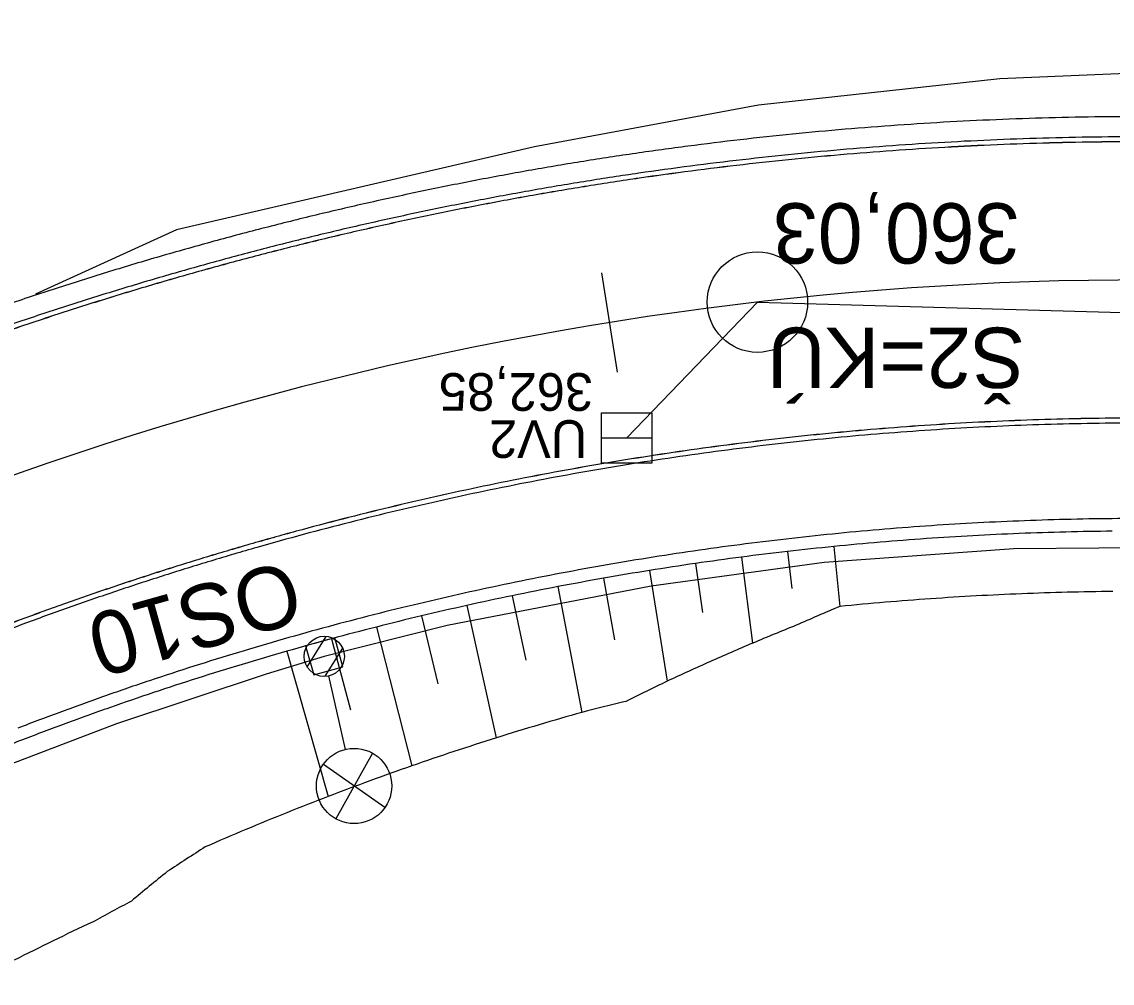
# Model space of a CAD drawing. Extents: x -783978 to -783565, y -1064821 to -1064596.
# Drawn here: x -783930.06 to -783908.35, y -1064751.46 to -1064732.32 of the extents above; entities that cross this region are included whole.
import ezdxf

# ---------------------------------------------------------------- set-up
doc = ezdxf.new("R2010")
doc.units = 0
for name, color, linetype in [('SO 01_31_01', 7, 'Continuous'), ('SO 01_50_01', 7, 'Continuous'), ('SO 01_86_02', 7, 'Continuous')]:
    doc.layers.add(name, color=color, linetype=linetype)

msp = doc.modelspace()

# ---------------------------------------------------------------- linework, layer by layer
at = {"layer": 'SO 01_31_01'}
msp.add_line((-783915.414, -1064737.9), (-783918.017, -1064740.603), dxfattribs=at)
for points in [[(-783915.414, -1064737.9), (-783878.441, -1064738.947), (-783868.99, -1064750.07)], [(-783918.517, -1064740.603), (-783918.517, -1064740.103), (-783917.517, -1064740.103), (-783917.517, -1064741.103), (-783918.517, -1064741.103), (-783918.517, -1064740.603), (-783917.517, -1064740.603)]]:
    msp.add_lwpolyline(points, dxfattribs=at)
msp.add_circle((-783915.414, -1064737.9), 1, dxfattribs=at)
at = {"layer": 'SO 01_50_01'}
for p, q in [((-783918.198, -1064739.294), (-783918.515, -1064737.319)), ((-783913.893, -1064742.765), (-783913.774, -1064743.959)), ((-783915.732, -1064742.977), (-783915.509, -1064744.689)), ((-783914.814, -1064742.864), (-783914.729, -1064743.599)), ((-783917.563, -1064743.243), (-783917.209, -1064745.446)), ((-783916.649, -1064743.103), (-783916.507, -1064744.081)), ((-783918.476, -1064743.397), (-783918.26, -1064744.626)), ((-783919.386, -1064743.564), (-783918.907, -1064746.067)), ((-783920.294, -1064743.745), (-783920.028, -1064745.03)), ((-783921.198, -1064743.939), (-783920.612, -1064746.574)), ((-783922.1, -1064744.147), (-783921.778, -1064745.497)), ((-783922.999, -1064744.368), (-783922.296, -1064747.133)), ((-783923.894, -1064744.603), (-783923.512, -1064746.017)), ((-783924.785, -1064744.851), (-783923.958, -1064747.741))]:
    msp.add_line(p, q, dxfattribs=at)
msp.add_lwpolyline([(-783892.218, -1064732.32), (-783899.264, -1064732.985), (-783903.473, -1064733.076), (-783906.328, -1064733.273), (-783910.587, -1064733.457), (-783915.392, -1064733.98), (-783919.851, -1064734.807), (-783926.976, -1064736.461), (-783929.783, -1064737.741)], dxfattribs=at)
for centre, radius, start, end in [((-783907.727, -1064804.458), 70.25, 93.14253, 93.99769), ((-783907.727, -1064804.458), 70.25, 93.14253, 93.99769), ((-783907.727, -1064804.458), 70.25, 93.14253, 93.99769), ((-783907.727, -1064804.458), 70.25, 92.28736, 93.14253), ((-783907.727, -1064804.458), 70.25, 92.28736, 93.14253), ((-783907.727, -1064804.458), 70.25, 92.28736, 93.14253), ((-783907.727, -1064804.458), 70.25, 91.4322, 92.28736), ((-783907.727, -1064804.458), 70.25, 91.4322, 92.28736), ((-783907.727, -1064804.458), 70.25, 91.4322, 92.28736), ((-783907.727, -1064804.458), 70.25, 90.57704, 91.4322), ((-783907.727, -1064804.458), 70.25, 90.57704, 91.4322), ((-783907.727, -1064804.458), 70.25, 90.57704, 91.4322), ((-783907.727, -1064804.458), 70.25, 89.72188, 90.57704), ((-783907.727, -1064804.458), 70.25, 89.72188, 90.57704), ((-783907.727, -1064804.458), 70.25, 89.72188, 90.57704), ((-783907.727, -1064804.458), 70.25, 95.70801, 96.56317), ((-783907.727, -1064804.458), 70.25, 95.70801, 96.56317), ((-783907.727, -1064804.458), 70.25, 95.70801, 96.56317), ((-783907.727, -1064804.458), 70.25, 94.85285, 95.70801), ((-783907.727, -1064804.458), 70.25, 94.85285, 95.70801), ((-783907.727, -1064804.458), 70.25, 94.85285, 95.70801), ((-783907.727, -1064804.458), 70.25, 93.99769, 94.85285), ((-783907.727, -1064804.458), 70.25, 93.99769, 94.85285), ((-783907.727, -1064804.458), 70.25, 93.99769, 94.85285), ((-783907.727, -1064804.458), 70.25, 97.41833, 98.27349), ((-783907.727, -1064804.458), 70.25, 97.41833, 98.27349), ((-783907.727, -1064804.458), 70.25, 97.41833, 98.27349), ((-783907.727, -1064804.458), 70.25, 96.56317, 97.41833), ((-783907.727, -1064804.458), 70.25, 96.56317, 97.41833), ((-783907.727, -1064804.458), 70.25, 96.56317, 97.41833), ((-783907.727, -1064804.458), 69.85, 93.99769, 94.85285), ((-783907.727, -1064804.458), 69.85, 93.14253, 93.99769), ((-783907.727, -1064804.458), 69.85, 92.28736, 93.14253), ((-783907.727, -1064804.458), 69.751, 92.28736, 93.14253), ((-783907.727, -1064804.458), 69.75, 92.28736, 93.14253), ((-783907.727, -1064804.458), 69.85, 91.4322, 92.28736), ((-783907.727, -1064804.458), 69.751, 91.4322, 92.28736), ((-783907.727, -1064804.458), 69.75, 91.4322, 92.28736), ((-783907.727, -1064804.458), 69.85, 90.57704, 91.4322), ((-783907.727, -1064804.458), 69.751, 90.57704, 91.4322), ((-783907.727, -1064804.458), 69.75, 90.57704, 91.4322), ((-783907.727, -1064804.458), 69.85, 89.72188, 90.57704), ((-783907.727, -1064804.458), 69.751, 89.72188, 90.57704), ((-783907.727, -1064804.458), 69.75, 89.72188, 90.57704), ((-783907.727, -1064804.458), 70.25, 98.27349, 99.12865), ((-783907.727, -1064804.458), 70.25, 98.27349, 99.12865), ((-783907.727, -1064804.458), 70.25, 98.27349, 99.12865), ((-783907.727, -1064804.458), 69.85, 95.70801, 96.56317), ((-783907.727, -1064804.458), 69.85, 94.85285, 95.70801), ((-783907.727, -1064804.458), 69.751, 94.85285, 95.70801), ((-783907.727, -1064804.458), 69.75, 94.85285, 95.70801), ((-783907.727, -1064804.458), 69.751, 93.99769, 94.85285), ((-783907.727, -1064804.458), 69.75, 93.99769, 94.85285), ((-783907.727, -1064804.458), 69.751, 93.14253, 93.99769), ((-783907.727, -1064804.458), 69.75, 93.14253, 93.99769), ((-783907.727, -1064804.458), 70.25, 99.12865, 99.98381), ((-783907.727, -1064804.458), 70.25, 99.12865, 99.98381), ((-783907.727, -1064804.458), 70.25, 99.12865, 99.98381), ((-783907.727, -1064804.458), 69.85, 97.41833, 98.27349), ((-783907.727, -1064804.458), 69.85, 96.56317, 97.41833), ((-783907.727, -1064804.458), 69.751, 96.56317, 97.41833), ((-783907.727, -1064804.458), 69.75, 96.56317, 97.41833), ((-783907.727, -1064804.458), 69.751, 95.70801, 96.56317), ((-783907.727, -1064804.458), 69.75, 95.70801, 96.56317), ((-783907.727, -1064804.458), 70.25, 99.98381, 100.83897), ((-783907.727, -1064804.458), 70.25, 99.98381, 100.83897), ((-783907.727, -1064804.458), 70.25, 99.98381, 100.83897), ((-783907.727, -1064804.458), 69.85, 98.27349, 99.12865), ((-783907.727, -1064804.458), 69.751, 98.27349, 99.12865), ((-783907.727, -1064804.458), 69.75, 98.27349, 99.12865), ((-783907.727, -1064804.458), 69.751, 97.41833, 98.27349), ((-783907.727, -1064804.458), 69.75, 97.41833, 98.27349), ((-783907.727, -1064804.458), 70.25, 101.69413, 102.5493), ((-783907.727, -1064804.458), 70.25, 101.69413, 102.5493), ((-783907.727, -1064804.458), 70.25, 101.69413, 102.5493), ((-783907.727, -1064804.458), 70.25, 100.83897, 101.69413), ((-783907.727, -1064804.458), 70.25, 100.83897, 101.69413), ((-783907.727, -1064804.458), 70.25, 100.83897, 101.69413), ((-783907.727, -1064804.458), 69.85, 99.98381, 100.83897), ((-783907.727, -1064804.458), 69.85, 99.12865, 99.98381), ((-783907.727, -1064804.458), 69.751, 99.12865, 99.98381), ((-783907.727, -1064804.458), 69.75, 99.12865, 99.98381), ((-783907.727, -1064804.458), 70.25, 102.5493, 103.40446), ((-783907.727, -1064804.458), 70.25, 102.5493, 103.40446), ((-783907.727, -1064804.458), 70.25, 102.5493, 103.40446), ((-783907.727, -1064804.458), 69.85, 100.83897, 101.69413), ((-783907.727, -1064804.458), 69.751, 99.98381, 100.83897), ((-783907.727, -1064804.458), 69.75, 99.98381, 100.83897), ((-783907.727, -1064804.458), 69.85, 101.69413, 102.5493), ((-783907.727, -1064804.458), 69.751, 100.83897, 101.69413), ((-783907.727, -1064804.458), 69.75, 100.83897, 101.69413), ((-783907.727, -1064804.458), 70.25, 103.40446, 104.25962), ((-783907.727, -1064804.458), 70.25, 103.40446, 104.25962), ((-783907.727, -1064804.458), 70.25, 103.40446, 104.25962), ((-783907.727, -1064804.458), 69.85, 102.5493, 103.40446), ((-783907.727, -1064804.458), 69.751, 101.69413, 102.5493), ((-783907.727, -1064804.458), 69.75, 101.69413, 102.5493), ((-783907.727, -1064804.458), 70.25, 104.25962, 105.11478), ((-783907.727, -1064804.458), 70.25, 104.25962, 105.11478), ((-783907.727, -1064804.458), 70.25, 104.25962, 105.11478), ((-783907.727, -1064804.458), 69.85, 103.40446, 104.25962), ((-783907.727, -1064804.458), 69.751, 102.5493, 103.40446), ((-783907.727, -1064804.458), 69.75, 102.5493, 103.40446), ((-783907.727, -1064804.458), 70.25, 105.11478, 105.96994), ((-783907.727, -1064804.458), 70.25, 105.11478, 105.96994), ((-783907.727, -1064804.458), 70.25, 105.11478, 105.96994), ((-783907.727, -1064804.458), 69.751, 103.40446, 104.25962), ((-783907.727, -1064804.458), 69.75, 103.40446, 104.25962), ((-783907.727, -1064804.458), 70.25, 105.96994, 106.8251), ((-783907.727, -1064804.458), 70.25, 105.96994, 106.8251), ((-783907.727, -1064804.458), 70.25, 105.96994, 106.8251), ((-783907.727, -1064804.458), 69.85, 104.25962, 105.11478), ((-783907.727, -1064804.458), 69.751, 104.25962, 105.11478), ((-783907.727, -1064804.458), 69.75, 104.25962, 105.11478), ((-783907.727, -1064804.458), 69.85, 105.11478, 105.96994), ((-783907.727, -1064804.458), 69.751, 105.11478, 105.96994), ((-783907.727, -1064804.458), 69.75, 105.11478, 105.96994), ((-783907.727, -1064804.458), 70.25, 106.8251, 107.68026), ((-783907.727, -1064804.458), 70.25, 106.8251, 107.68026), ((-783907.727, -1064804.458), 70.25, 106.8251, 107.68026), ((-783907.727, -1064804.458), 69.85, 105.96994, 106.8251), ((-783907.727, -1064804.458), 69.751, 105.96994, 106.8251), ((-783907.727, -1064804.458), 69.75, 105.96994, 106.8251), ((-783907.727, -1064804.458), 67, 86.89792, 119.07174), ((-783907.727, -1064804.458), 70.25, 107.68026, 108.53542), ((-783907.727, -1064804.458), 70.25, 107.68026, 108.53542), ((-783907.727, -1064804.458), 70.25, 107.68026, 108.53542), ((-783907.727, -1064804.458), 69.85, 106.8251, 107.68026), ((-783907.727, -1064804.458), 69.751, 106.8251, 107.68026), ((-783907.727, -1064804.458), 69.75, 106.8251, 107.68026), ((-783907.727, -1064804.458), 70.25, 108.53542, 109.39058), ((-783907.727, -1064804.458), 70.25, 108.53542, 109.39058), ((-783907.727, -1064804.458), 70.25, 108.53542, 109.39058), ((-783907.727, -1064804.458), 69.85, 107.68026, 108.53542), ((-783907.727, -1064804.458), 69.751, 107.68026, 108.53542), ((-783907.727, -1064804.458), 69.75, 107.68026, 108.53542), ((-783907.727, -1064804.458), 69.85, 108.53542, 109.39058), ((-783907.727, -1064804.458), 69.751, 108.53542, 109.39058), ((-783907.727, -1064804.458), 69.75, 108.53542, 109.39058), ((-783907.727, -1064804.458), 64.25, 91.4322, 92.28736), ((-783907.727, -1064804.458), 64.249, 91.4322, 92.28736), ((-783907.727, -1064804.458), 64.25, 90.57704, 91.4322), ((-783907.727, -1064804.458), 64.249, 90.57704, 91.4322), ((-783907.727, -1064804.458), 64.25, 89.72188, 90.57704), ((-783907.727, -1064804.458), 64.249, 89.72188, 90.57704), ((-783907.727, -1064804.458), 64.25, 94.85285, 95.70801), ((-783907.727, -1064804.458), 64.249, 94.85285, 95.70801), ((-783907.727, -1064804.458), 64.25, 93.99769, 94.85285), ((-783907.727, -1064804.458), 64.249, 93.99769, 94.85285), ((-783907.727, -1064804.458), 64.25, 93.14253, 93.99769), ((-783907.727, -1064804.458), 64.249, 93.14253, 93.99769), ((-783907.727, -1064804.458), 64.15, 93.14253, 93.99769), ((-783907.727, -1064804.458), 64.25, 92.28736, 93.14253), ((-783907.727, -1064804.458), 64.249, 92.28736, 93.14253), ((-783907.727, -1064804.458), 64.15, 92.28736, 93.14253), ((-783907.727, -1064804.458), 64.15, 91.4322, 92.28736), ((-783907.727, -1064804.458), 64.15, 90.57704, 91.4322), ((-783907.727, -1064804.458), 64.15, 89.72188, 90.57704), ((-783907.727, -1064804.458), 64.25, 96.56317, 97.41833), ((-783907.727, -1064804.458), 64.249, 96.56317, 97.41833), ((-783907.727, -1064804.458), 64.25, 95.70801, 96.56317), ((-783907.727, -1064804.458), 64.249, 95.70801, 96.56317), ((-783907.727, -1064804.458), 64.15, 95.70801, 96.56317), ((-783907.727, -1064804.458), 64.15, 94.85285, 95.70801), ((-783907.727, -1064804.458), 64.15, 93.99769, 94.85285), ((-783907.727, -1064804.458), 64.25, 98.27349, 99.12865), ((-783907.727, -1064804.458), 64.249, 98.27349, 99.12865), ((-783907.727, -1064804.458), 64.25, 97.41833, 98.27349), ((-783907.727, -1064804.458), 64.249, 97.41833, 98.27349), ((-783907.727, -1064804.458), 64.15, 97.41833, 98.27349), ((-783907.727, -1064804.458), 64.15, 96.56317, 97.41833), ((-783907.727, -1064804.458), 64.25, 99.12865, 99.98381), ((-783907.727, -1064804.458), 64.249, 99.12865, 99.98381), ((-783907.727, -1064804.458), 64.15, 98.27349, 99.12865), ((-783907.727, -1064804.458), 64.25, 99.98381, 100.83897), ((-783907.727, -1064804.458), 64.249, 99.98381, 100.83897), ((-783907.727, -1064804.458), 64.15, 99.98381, 100.83897), ((-783907.727, -1064804.458), 64.15, 99.12865, 99.98381), ((-783907.727, -1064804.458), 64.25, 100.83897, 101.69413), ((-783907.727, -1064804.458), 64.249, 100.83897, 101.69413), ((-783907.727, -1064804.458), 64.15, 100.83897, 101.69413), ((-783907.727, -1064804.458), 64.25, 102.5493, 103.40446), ((-783907.727, -1064804.458), 64.249, 102.5493, 103.40446), ((-783907.727, -1064804.458), 64.25, 101.69413, 102.5493), ((-783907.727, -1064804.458), 64.249, 101.69413, 102.5493), ((-783907.727, -1064804.458), 64.15, 101.69413, 102.5493), ((-783907.727, -1064804.458), 64.25, 103.40446, 104.25962), ((-783907.727, -1064804.458), 64.249, 103.40446, 104.25962), ((-783907.727, -1064804.458), 64.15, 102.5493, 103.40446), ((-783907.727, -1064804.458), 64.15, 103.40446, 104.25962), ((-783907.727, -1064804.458), 64.25, 104.25962, 105.11478), ((-783907.727, -1064804.458), 64.249, 104.25962, 105.11478), ((-783907.727, -1064804.458), 64.15, 104.25962, 105.11478), ((-783907.727, -1064804.458), 62.25, 93.99769, 94.85285), ((-783907.727, -1064804.458), 62.25, 93.14253, 93.99769), ((-783907.727, -1064804.458), 62.25, 92.28736, 93.14253), ((-783907.727, -1064804.458), 62.25, 91.4322, 92.28736), ((-783907.727, -1064804.458), 62.25, 90.57704, 91.4322), ((-783907.727, -1064804.458), 62.25, 89.72188, 90.57704), ((-783907.727, -1064804.458), 64.25, 105.11478, 105.96994), ((-783907.727, -1064804.458), 64.249, 105.11478, 105.96994), ((-783907.727, -1064804.458), 64.15, 105.11478, 105.96994), ((-783907.727, -1064804.458), 62.25, 96.56317, 97.41833), ((-783907.727, -1064804.458), 62.25, 95.70801, 96.56317), ((-783907.727, -1064804.458), 62.25, 94.85285, 95.70801), ((-783907.727, -1064804.458), 62, 93.99769, 94.85285), ((-783907.727, -1064804.458), 62, 93.99769, 94.85285), ((-783907.727, -1064804.458), 62, 93.99769, 94.85285), ((-783907.727, -1064804.458), 62, 93.14253, 93.99769), ((-783907.727, -1064804.458), 62, 93.14253, 93.99769), ((-783907.727, -1064804.458), 62, 93.14253, 93.99769), ((-783907.727, -1064804.458), 62, 92.28736, 93.14253), ((-783907.727, -1064804.458), 62, 92.28736, 93.14253), ((-783907.727, -1064804.458), 62, 92.28736, 93.14253), ((-783907.727, -1064804.458), 62, 91.4322, 92.28736), ((-783907.727, -1064804.458), 62, 91.4322, 92.28736), ((-783907.727, -1064804.458), 62, 91.4322, 92.28736), ((-783907.727, -1064804.458), 62, 90.57704, 91.4322), ((-783907.727, -1064804.458), 62, 90.57704, 91.4322), ((-783907.727, -1064804.458), 62, 90.57704, 91.4322), ((-783907.727, -1064804.458), 64.25, 105.96994, 106.8251), ((-783907.727, -1064804.458), 64.249, 105.96994, 106.8251), ((-783907.727, -1064804.458), 64.15, 105.96994, 106.8251), ((-783907.727, -1064804.458), 62.25, 97.41833, 98.27349), ((-783907.727, -1064804.458), 62, 95.70801, 96.56317), ((-783907.727, -1064804.458), 62, 95.70801, 96.56317), ((-783907.727, -1064804.458), 62, 95.70801, 96.56317), ((-783907.727, -1064804.458), 62, 94.85285, 95.70801), ((-783907.727, -1064804.458), 62, 94.85285, 95.70801), ((-783907.727, -1064804.458), 62, 94.85285, 95.70801), ((-783907.727, -1064804.458), 64.25, 106.8251, 107.68026), ((-783907.727, -1064804.458), 64.249, 106.8251, 107.68026), ((-783907.727, -1064804.458), 64.15, 106.8251, 107.68026), ((-783907.727, -1064804.458), 62.25, 99.12865, 99.98381), ((-783907.727, -1064804.458), 62.25, 98.27349, 99.12865), ((-783907.727, -1064804.458), 62, 97.41833, 98.27349), ((-783907.727, -1064804.458), 62, 97.41833, 98.27349), ((-783907.727, -1064804.458), 62, 97.41833, 98.27349), ((-783907.727, -1064804.458), 62, 96.56317, 97.41833), ((-783907.727, -1064804.458), 62, 96.56317, 97.41833), ((-783907.727, -1064804.458), 62, 96.56317, 97.41833), ((-783907.727, -1064804.458), 64.25, 107.68026, 108.53542), ((-783907.727, -1064804.458), 64.249, 107.68026, 108.53542), ((-783907.727, -1064804.458), 62.25, 99.98381, 100.83897), ((-783907.727, -1064804.458), 62, 99.12865, 99.98381), ((-783907.727, -1064804.458), 62, 99.12865, 99.98381), ((-783907.727, -1064804.458), 62, 99.12865, 99.98381), ((-783907.727, -1064804.458), 62, 98.27349, 99.12865), ((-783907.727, -1064804.458), 62, 98.27349, 99.12865), ((-783907.727, -1064804.458), 62, 98.27349, 99.12865), ((-783907.727, -1064804.458), 64.15, 107.68026, 108.53542), ((-783907.727, -1064804.458), 62.25, 100.83897, 101.69413), ((-783907.727, -1064804.458), 62, 99.98381, 100.83897), ((-783907.727, -1064804.458), 62, 99.98381, 100.83897), ((-783907.727, -1064804.458), 62, 99.98381, 100.83897), ((-783907.727, -1064804.458), 64.249, 108.53542, 109.39058), ((-783907.727, -1064804.458), 64.25, 108.53542, 109.39058), ((-783907.727, -1064804.458), 64.15, 108.53542, 109.39058), ((-783907.727, -1064804.458), 62.25, 102.5493, 103.40446), ((-783907.727, -1064804.458), 62.25, 101.69413, 102.5493), ((-783907.727, -1064804.458), 62, 100.83897, 101.69413), ((-783907.727, -1064804.458), 62, 100.83897, 101.69413), ((-783907.727, -1064804.458), 62, 100.83897, 101.69413), ((-783907.727, -1064804.458), 60.8, 91.4322, 92.28736), ((-783907.727, -1064804.458), 60.8, 90.57704, 91.4322), ((-783907.727, -1064804.458), 64.25, 109.39058, 110.24574), ((-783907.727, -1064804.458), 64.249, 109.39058, 110.24574), ((-783907.727, -1064804.458), 62.25, 103.40446, 104.25962), ((-783907.727, -1064804.458), 62, 101.69413, 102.5493), ((-783907.727, -1064804.458), 62, 101.69413, 102.5493), ((-783907.727, -1064804.458), 62, 101.69413, 102.5493), ((-783907.727, -1064804.458), 60.8, 94.85285, 95.70801), ((-783907.727, -1064804.458), 60.8, 93.99769, 94.85285), ((-783907.727, -1064804.458), 60.8, 93.14253, 93.99769), ((-783907.727, -1064804.458), 60.8, 92.28736, 93.14253), ((-783907.727, -1064804.458), 64.15, 109.39058, 110.24574), ((-783907.727, -1064804.458), 62.25, 104.25962, 105.11478), ((-783907.727, -1064804.458), 62, 102.5493, 103.40446), ((-783907.727, -1064804.458), 62, 102.5493, 103.40446), ((-783907.727, -1064804.458), 62, 102.5493, 103.40446), ((-783890.188, -1064799.998), 60.8, 112.82578, 113.71861), ((-783907.727, -1064804.458), 64.25, 110.24574, 111.1009), ((-783907.727, -1064804.458), 64.249, 110.24574, 111.1009), ((-783907.727, -1064804.458), 64.15, 110.24574, 111.1009), ((-783907.727, -1064804.458), 62, 103.40446, 104.25962), ((-783907.727, -1064804.458), 62, 103.40446, 104.25962), ((-783907.727, -1064804.458), 62, 103.40446, 104.25962), ((-783892.048, -1064800.478), 60.521, 111.9237, 112.80879), ((-783907.727, -1064804.458), 62.25, 105.11478, 105.96994), ((-783907.727, -1064804.458), 62, 104.25962, 105.11478), ((-783907.727, -1064804.458), 62, 104.25962, 105.11478), ((-783907.727, -1064804.458), 62, 104.25962, 105.11478), ((-783907.727, -1064804.458), 62.25, 105.96994, 106.8251), ((-783907.727, -1064804.458), 62, 105.11478, 105.96994), ((-783907.727, -1064804.458), 62, 105.11478, 105.96994), ((-783907.727, -1064804.458), 62, 105.11478, 105.96994), ((-783891.943, -1064800.164), 60.273, 113.01561, 113.90168), ((-783907.727, -1064804.458), 62.25, 106.8251, 107.68026), ((-783907.727, -1064804.458), 62, 105.96994, 106.8251), ((-783907.727, -1064804.458), 62, 105.96994, 106.8251), ((-783907.727, -1064804.458), 62, 105.96994, 106.8251), ((-783907.727, -1064804.458), 62.25, 107.68026, 108.53542), ((-783907.727, -1064804.458), 62, 106.8251, 107.68026), ((-783907.727, -1064804.458), 62, 106.8251, 107.68026), ((-783907.727, -1064804.458), 62, 106.8251, 107.68026), ((-783891.861, -1064799.853), 60.022, 114.0944, 114.98142), ((-783907.727, -1064804.458), 62.25, 108.53542, 109.39058), ((-783907.727, -1064804.458), 62, 107.68026, 108.53542), ((-783907.727, -1064804.458), 62, 107.68026, 108.53542), ((-783907.727, -1064804.458), 62, 107.68026, 108.53542), ((-783891.385, -1064799.348), 59.768, 115.59877, 116.48863), ((-783907.727, -1064804.458), 62.25, 109.39058, 110.24574), ((-783907.727, -1064804.458), 62, 108.53542, 109.39058), ((-783907.727, -1064804.458), 62, 108.53542, 109.39058), ((-783907.727, -1064804.458), 62, 108.53542, 109.39058), ((-783904.241, -1064803.736), 59.505, 103.41259, 104.26891), ((-783907.727, -1064804.458), 62.25, 110.24574, 111.1009), ((-783907.727, -1064804.458), 62, 109.39058, 110.24574), ((-783907.727, -1064804.458), 62, 109.39058, 110.24574), ((-783907.727, -1064804.458), 62, 109.39058, 110.24574), ((-783902.795, -1064803.294), 59.452, 105.7239, 106.58164), ((-783907.727, -1064804.458), 62, 110.24574, 111.1009), ((-783907.727, -1064804.458), 62, 110.24574, 111.1009), ((-783907.727, -1064804.458), 62, 110.24574, 111.1009), ((-783902.796, -1064803.215), 59.376, 106.60288, 107.46064), ((-783907.727, -1064804.458), 62, 111.1009, 111.95606), ((-783907.727, -1064804.458), 62, 111.1009, 111.95606), ((-783907.727, -1064804.458), 62, 111.1009, 111.95606), ((-783902.808, -1064803.139), 59.3, 107.47158, 108.32936), ((-783902.807, -1064803.058), 59.224, 108.3546, 109.21241), ((-783902.812, -1064802.979), 59.147, 109.23359, 110.09143), ((-783902.817, -1064802.899), 59.07, 110.11307, 110.97094), ((-783902.828, -1064802.821), 58.993, 110.98792, 111.84581), ((-783902.829, -1064802.738), 58.916, 111.87505, 112.73298), ((-783902.836, -1064802.656), 58.838, 112.7576, 113.61557), ((-783894.729, -1064798.236), 58.76, 122.62183, 123.5019), ((-783890.352, -1064794.757), 58.541, 128.96209, 129.86743), ((-783900.631, -1064801.288), 58.23, 117.89845, 118.76044), ((-783904.087, -1064802.909), 58.114, 115.00226, 115.85897), ((-783903.892, -1064802.748), 58.054, 116.10066, 116.9576)]:
    msp.add_arc(centre, radius, start, end, dxfattribs=at)
at = {"layer": 'SO 01_86_02'}
for p, q in [((-783924.005, -1064744.558), (-783924.38, -1064745.157)), ((-783923.677, -1064744.787), (-783924.029, -1064745.349)), ((-783923.612, -1064746.804), (-783923.948, -1064745.342)), ((-783923.08, -1064746.878), (-783923.807, -1064748.188)), ((-783922.831, -1064747.963), (-783924.056, -1064747.103))]:
    msp.add_line(p, q, dxfattribs=at)
msp.add_lwpolyline([(-783878.171, -1064745.018), (-783878.186, -1064744.275), (-783880.673, -1064744.123), (-783888.395, -1064743.656), (-783896.118, -1064743.19), (-783902.642, -1064742.943), (-783906.922, -1064742.781), (-783908.615, -1064742.797), (-783910.308, -1064742.813), (-783914.084, -1064743.083), (-783917.528, -1064743.556), (-783921.591, -1064744.335), (-783924.038, -1064744.952), (-783925.195, -1064745.304), (-783928.174, -1064746.293), (-783932.665, -1064748.008), (-783936.408, -1064749.851), (-783943.728, -1064753.874), (-783953.702, -1064759.355), (-783962.96, -1064764.568)], dxfattribs=at)
msp.add_lwpolyline([(-783924.246, -1064745.322), (-783923.669, -1064745.16), (-783923.83, -1064744.582), (-783924.408, -1064744.744)], close=True, dxfattribs=at)
for centre, radius in [((-783924.038, -1064744.952), 0.4), ((-783923.444, -1064747.533), 0.749)]:
    msp.add_circle(centre, radius, dxfattribs=at)

# ---------------------------------------------------------------- texts
at = {"layer": 'SO 01_31_01'}
for s, height, p in [('360,03', 1.2, (-783910.197, -1064735.932)), ('Š2=KÚ', 1.2, (-783910.089, -1064738.408)), ('362,85', 0.75, (-783918.689, -1064739.314)), ('UV2', 0.75, (-783918.803, -1064740.251))]:
    msp.add_text(s, height=height, rotation=180, dxfattribs=at).set_placement(p)
at = {"layer": 'SO 01_86_02'}
msp.add_text('OS10', height=1.25, rotation=195.6157, dxfattribs=at).set_placement((-783924.721, -1064743.026))

doc.saveas('drawing.dxf')
